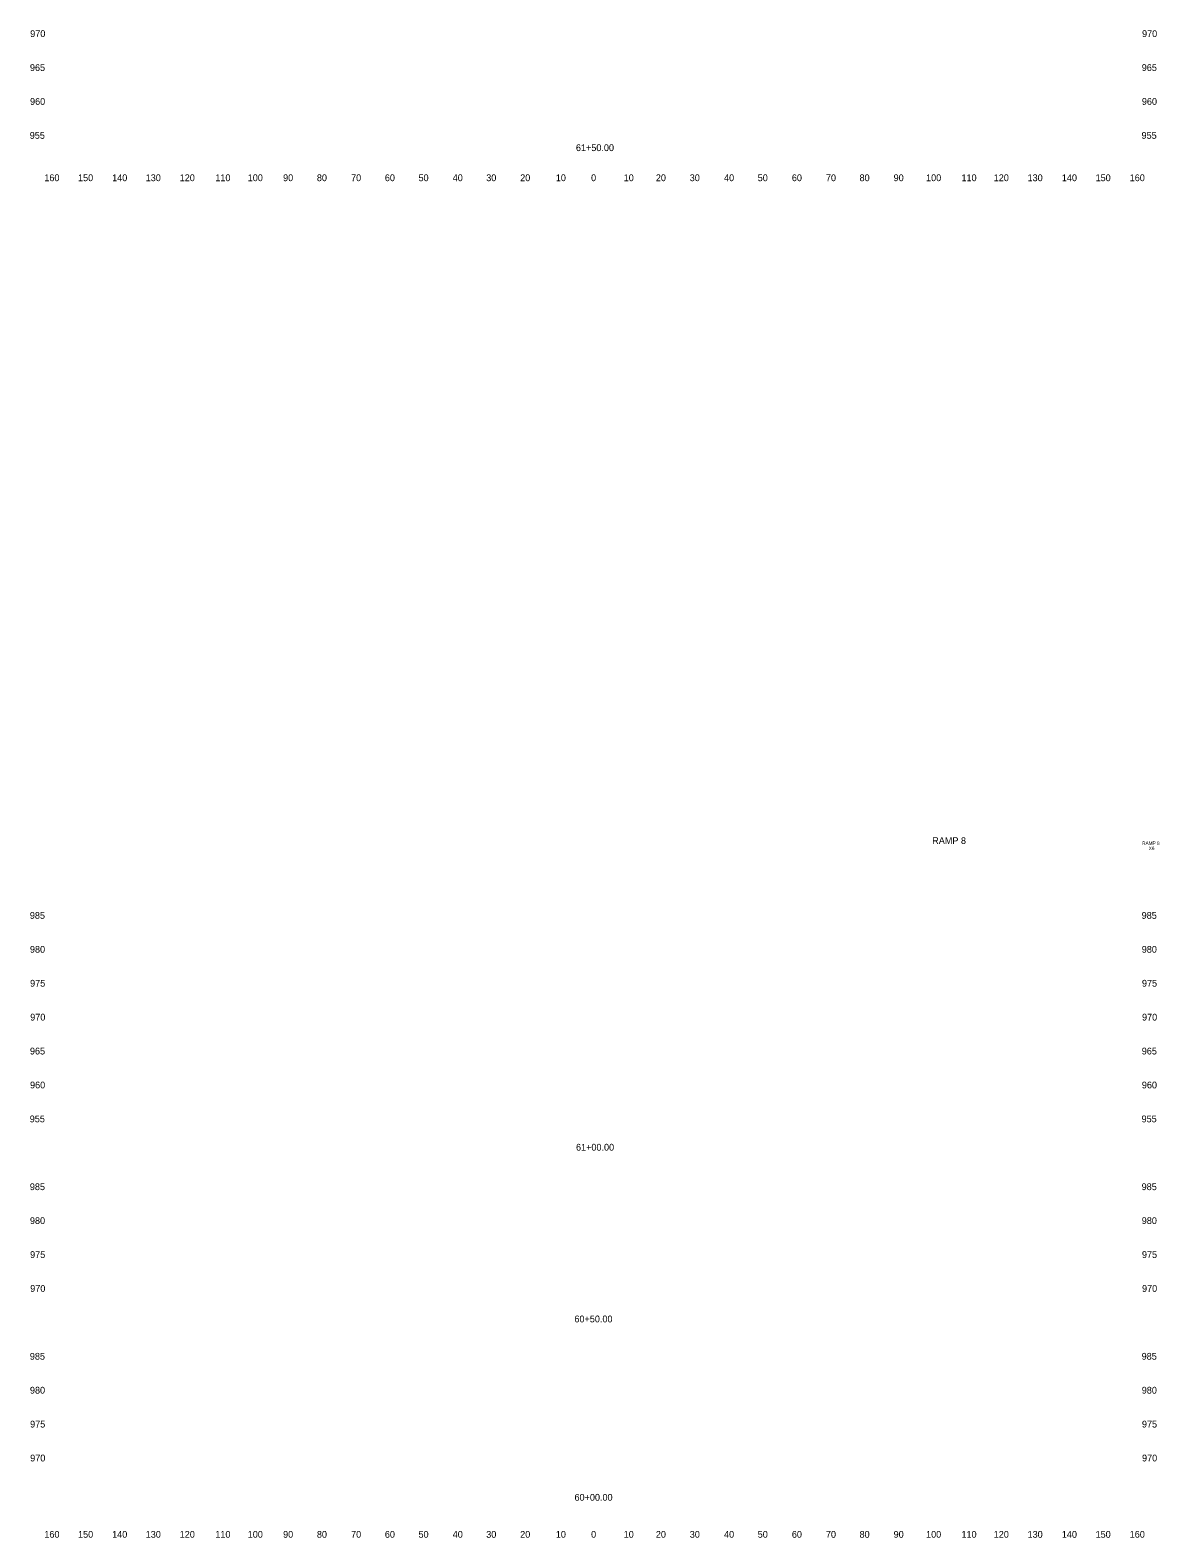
# Model space of a CAD drawing. Extents: x 4994 to 5843, y 4997 to 8804.
# Drawn here: x 4993.9 to 5326.7, y 6997.5 to 7442 of the extents above; entities that cross this region are included whole.
import ezdxf

# ---------------------------------------------------------------- set-up
doc = ezdxf.new("R2010")
doc.units = 0
for name, color, linetype in [('RD_SHT_ID', 7, 'Continuous'), ('RD_XS_TX_Offset', 7, 'Continuous'), ('RD_XS_TX_Station', 7, 'Continuous')]:
    doc.layers.add(name, color=color, linetype=linetype)

msp = doc.modelspace()

# ---------------------------------------------------------------- texts
at = {"layer": 'RD_SHT_ID'}
for s, height, p in [('RAMP 8', 2, (5259.88, 7202.06)), ('RAMP 8', 1, (5321.78, 7201.8)), ('X6', 1, (5323.71, 7200.3))]:
    msp.add_text(s, height=height, dxfattribs=at).set_placement(p)
at = {"layer": 'RD_XS_TX_Offset'}
for s, p in [('970', (4993.94, 7440)), ('970', (5321.74, 7440)), ('965', (4993.86, 7430)), ('965', (5321.66, 7430)), ('960', (4993.89, 7420)), ('960', (5321.69, 7420)), ('955', (4993.8, 7410)), ('955', (5321.6, 7410)), ('160', (4998.1, 7397.5)), ('150', (5008.04, 7397.5)), ('140', (5018.1, 7397.5)), ('130', (5027.99, 7397.5)), ('120', (5038.01, 7397.5)), ('110', (5048.51, 7397.5)), ('100', (5058.07, 7397.5)), ('90', (5068.5, 7397.5)), ('80', (5078.46, 7397.5)), ('70', (5088.54, 7397.5)), ('60', (5098.5, 7397.5)), ('50', (5108.43, 7397.5)), ('40', (5118.5, 7397.5)), ('30', (5128.39, 7397.5)), ('20', (5138.4, 7397.5)), ('10', (5148.91, 7397.5)), ('0', (5159.3, 7397.5)), ('0', (5159.3, 7397.5)), ('10', (5168.91, 7397.5)), ('20', (5178.4, 7397.5)), ('30', (5188.39, 7397.5)), ('40', (5198.5, 7397.5)), ('50', (5208.43, 7397.5)), ('60', (5218.5, 7397.5)), ('70', (5228.54, 7397.5)), ('80', (5238.46, 7397.5)), ('90', (5248.5, 7397.5)), ('100', (5258.07, 7397.5)), ('110', (5268.51, 7397.5)), ('120', (5278.01, 7397.5)), ('130', (5287.99, 7397.5)), ('140', (5298.1, 7397.5)), ('150', (5308.04, 7397.5)), ('160', (5318.1, 7397.5)), ('985', (4993.83, 7180)), ('985', (5321.63, 7180)), ('980', (4993.86, 7170)), ('980', (5321.66, 7170)), ('975', (4993.91, 7160)), ('975', (5321.71, 7160)), ('970', (4993.94, 7150)), ('970', (5321.74, 7150)), ('965', (4993.86, 7140)), ('965', (5321.66, 7140)), ('960', (4993.89, 7130)), ('960', (5321.69, 7130)), ('955', (4993.8, 7120)), ('955', (5321.6, 7120)), ('985', (4993.83, 7100)), ('985', (5321.63, 7100)), ('980', (4993.86, 7090)), ('980', (5321.66, 7090)), ('975', (4993.91, 7080)), ('975', (5321.71, 7080)), ('970', (4993.94, 7070)), ('970', (5321.74, 7070)), ('985', (4993.83, 7050)), ('985', (5321.63, 7050)), ('980', (4993.86, 7040)), ('980', (5321.66, 7040)), ('975', (4993.91, 7030)), ('975', (5321.71, 7030)), ('970', (4993.94, 7020)), ('970', (5321.74, 7020)), ('160', (4998.1, 6997.5)), ('150', (5008.04, 6997.5)), ('140', (5018.1, 6997.5)), ('130', (5027.99, 6997.5)), ('120', (5038.01, 6997.5)), ('110', (5048.51, 6997.5)), ('100', (5058.07, 6997.5)), ('90', (5068.5, 6997.5)), ('80', (5078.46, 6997.5)), ('70', (5088.54, 6997.5)), ('60', (5098.5, 6997.5)), ('50', (5108.43, 6997.5)), ('40', (5118.5, 6997.5)), ('30', (5128.39, 6997.5)), ('20', (5138.4, 6997.5)), ('10', (5148.91, 6997.5)), ('0', (5159.3, 6997.5)), ('0', (5159.3, 6997.5)), ('10', (5168.91, 6997.5)), ('20', (5178.4, 6997.5)), ('30', (5188.39, 6997.5)), ('40', (5198.5, 6997.5)), ('50', (5208.43, 6997.5)), ('60', (5218.5, 6997.5)), ('70', (5228.54, 6997.5)), ('80', (5238.46, 6997.5)), ('90', (5248.5, 6997.5)), ('100', (5258.07, 6997.5)), ('110', (5268.51, 6997.5)), ('120', (5278.01, 6997.5)), ('130', (5287.99, 6997.5)), ('140', (5298.1, 6997.5)), ('150', (5308.04, 6997.5)), ('160', (5318.1, 6997.5))]:
    msp.add_text(s, height=2, dxfattribs=at).set_placement(p)
at = {"layer": 'RD_XS_TX_Station'}
for s, p in [('61+50.00', (5154.83, 7406.37)), ('61+00.00', (5154.86, 7111.65)), ('60+50.00', (5154.39, 7061.02)), ('60+00.00', (5154.42, 7008.42))]:
    msp.add_text(s, height=2, dxfattribs=at).set_placement(p)

doc.saveas('drawing.dxf')
